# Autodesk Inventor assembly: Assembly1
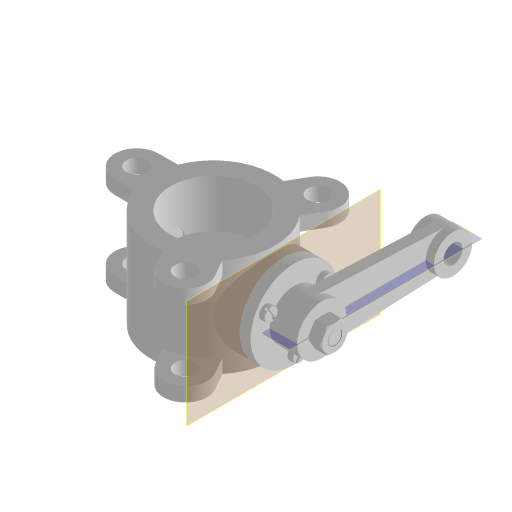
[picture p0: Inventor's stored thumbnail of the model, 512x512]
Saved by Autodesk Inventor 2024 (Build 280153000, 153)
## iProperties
Created: 2019-03
Part Number: Assembly1
Document SubType Name: Assembly
Designer: LENOVO-CADCIM
Author: LENOVO-CADCIM
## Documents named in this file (10)
- D:\PROJECTS\Project 2023\RESOURCES INVENTOR 2024\RESOURCES INVENTOR 2024\Inventor_2024_tut\Inventor_2024_tut\c10_Inv_2024_tut\c10_Inv_tut_2024\c10_tut01_inv\Butterfly Valve\Butterfly Valve Assembly.iam
- D:\PROJECTS\Project 2023\RESOURCES INVENTOR 2024\RESOURCES INVENTOR 2024\Inventor_2024_tut\Inventor_2024_tut\c10_Inv_2024_tut\c10_Inv_tut_2024\c10_tut01_inv\Butterfly Valve\Body.ipt
- D:\PROJECTS\Project 2023\RESOURCES INVENTOR 2024\RESOURCES INVENTOR 2024\Inventor_2024_tut\Inventor_2024_tut\c10_Inv_2024_tut\c10_Inv_tut_2024\c10_tut01_inv\Butterfly Valve\Shaft.ipt
- D:\PROJECTS\Project 2023\RESOURCES INVENTOR 2024\RESOURCES INVENTOR 2024\Inventor_2024_tut\Inventor_2024_tut\c10_Inv_2024_tut\c10_Inv_tut_2024\c10_tut01_inv\Butterfly Valve\Retainer.ipt
- D:\PROJECTS\Project 2023\RESOURCES INVENTOR 2024\RESOURCES INVENTOR 2024\Inventor_2024_tut\Inventor_2024_tut\c10_Inv_2024_tut\c10_Inv_tut_2024\c10_tut01_inv\Butterfly Valve\Arm1.ipt
- D:\PROJECTS\Project 2023\RESOURCES INVENTOR 2024\RESOURCES INVENTOR 2024\Inventor_2024_tut\Inventor_2024_tut\c10_Inv_2024_tut\c10_Inv_tut_2024\c10_tut01_inv\Butterfly Valve\Plate.ipt
- D:\PROJECTS\Project 2023\RESOURCES INVENTOR 2024\RESOURCES INVENTOR 2024\Inventor_2024_tut\Inventor_2024_tut\c10_Inv_2024_tut\c10_Inv_tut_2024\c10_tut01_inv\Butterfly Valve\scew1.ipt
- D:\PROJECTS\Project 2023\RESOURCES INVENTOR 2024\RESOURCES INVENTOR 2024\Inventor_2024_tut\Inventor_2024_tut\c10_Inv_2024_tut\c10_Inv_tut_2024\c10_tut01_inv\Butterfly Valve\Screw.ipt
- D:\PROJECTS\Project 2023\RESOURCES INVENTOR 2024\RESOURCES INVENTOR 2024\Inventor_2024_tut\Inventor_2024_tut\c10_Inv_2024_tut\c10_Inv_tut_2024\c10_tut01_inv\Butterfly Valve\Parallel key.ipt
- D:\PROJECTS\Project 2023\RESOURCES INVENTOR 2024\RESOURCES INVENTOR 2024\Inventor_2024_tut\Inventor_2024_tut\c10_Inv_2024_tut\c10_Inv_tut_2024\c10_tut01_inv\Butterfly Valve\Nut.ipt
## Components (12 placed, 9 different names)
1. Body:1 — Insert:1, Insert:2, Mate:1, Angle:2, Angle:3, Angle:4
2. Shaft:1 — Insert:1, Angle:2, Angle:3, Insert:3, Insert:4, Mate:3, Insert:11
3. Retainer:1 — Insert:2, Mate:1, Insert:7, Insert:10
4. Arm1:1 — Insert:10, Mate:2, Flush:1
5. Plate:1 — Insert:3, Insert:4, Insert:5, Insert:6
6. scew1:1 — Insert:5
7. scew1:2 — Insert:6
8. Parallel key:1 — Mate:2, Mate:3, Flush:1
9. Nut:1 — Insert:11, Angle:4
10. Screw:1 — Insert:7
11. Screw:2
12. Screw:3
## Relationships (16: Insert 9, Mate 3, Angle 3, Flush 1)
- Insert:1: Body:1 ↔ Shaft:1
- Insert:2: Body:1 ↔ Retainer:1
- Mate:1: Body:1 ↔ Retainer:1
- Angle:2: Body:1 ↔ Shaft:1
- Angle:3: Body:1 ↔ Shaft:1
- Insert:3: Shaft:1 ↔ Plate:1
- Insert:4: Shaft:1 ↔ Plate:1
- Insert:5: Plate:1 ↔ scew1:1
- Insert:6: Plate:1 ↔ scew1:2
- Insert:7: Retainer:1 ↔ Screw:1
- Insert:10: Retainer:1 ↔ Arm1:1
- Mate:2: Arm1:1 ↔ Parallel key:1
- Mate:3: Shaft:1 ↔ Parallel key:1
- Flush:1: Arm1:1 ↔ Parallel key:1
- Insert:11: Shaft:1 ↔ Nut:1
- Angle:4: Body:1 ↔ Nut:1
